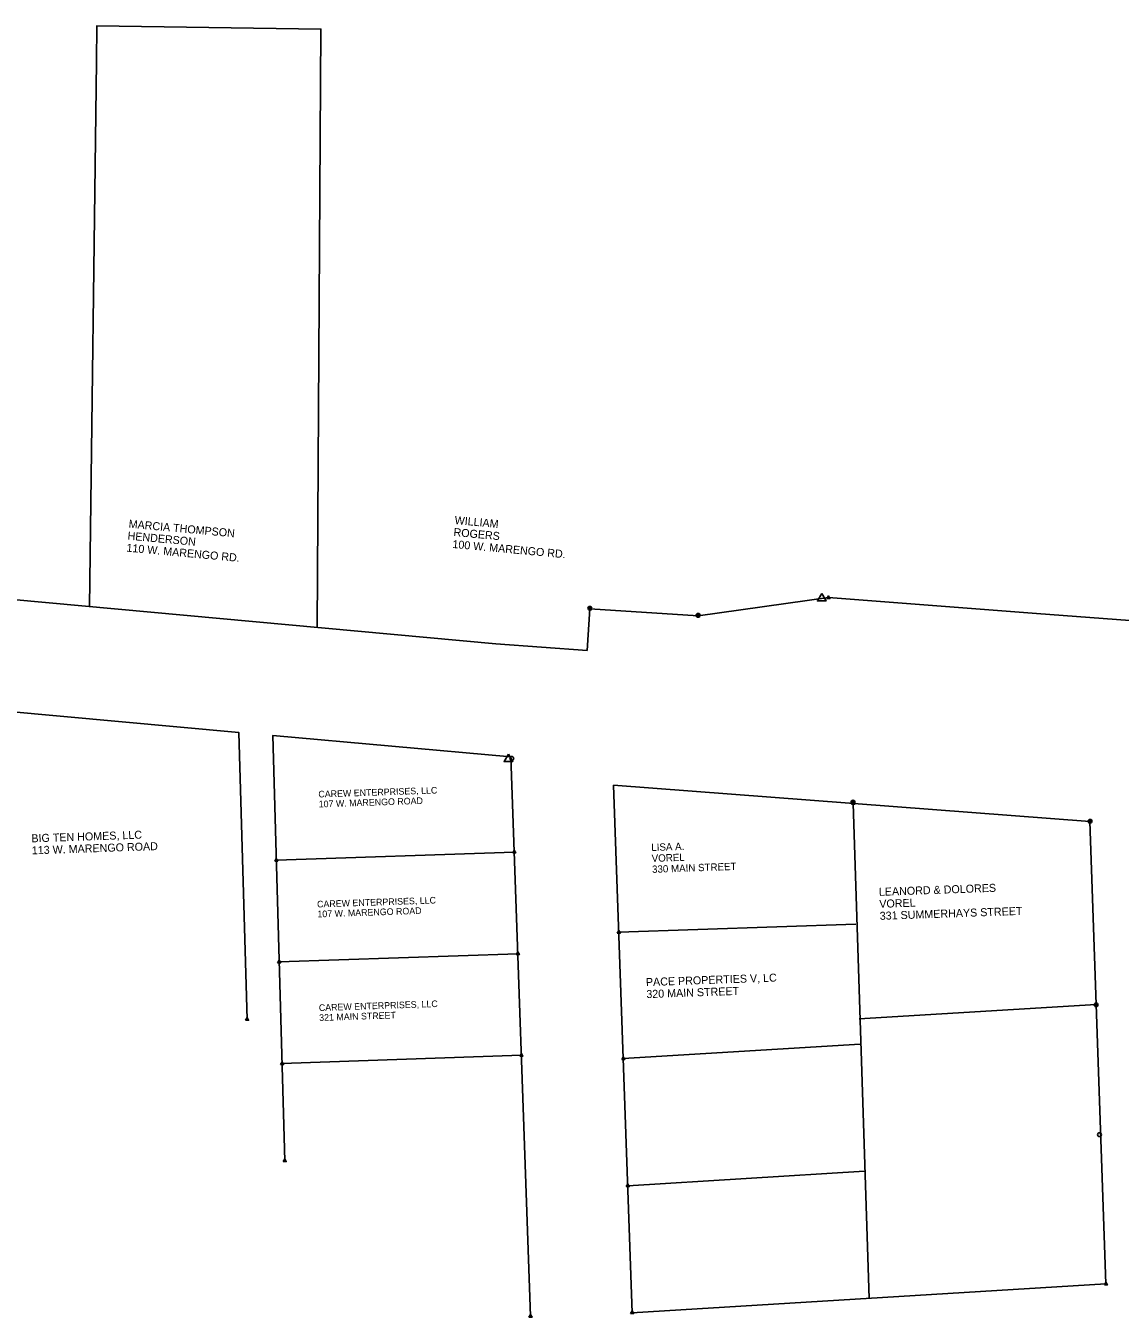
# Model space of a CAD drawing. Extents: x 20500076 to 20505422, y 7951999 to 7957351.
# Drawn here: x 20500631 to 20501277, y 7953599 to 7954361 of the extents above; entities that cross this region are included whole.
import ezdxf

# ---------------------------------------------------------------- set-up
doc = ezdxf.new("R2010")
doc.units = 0
for name, color, linetype in [('DisROW Existing', 7, 'Continuous'), ('DisROW Property Lines', 7, 'Continuous'), ('rowdsnSymbolsProposed', 7, 'Continuous'), ('SurControl', 7, 'Continuous'), ('SurSectionCorner', 7, 'Continuous'), ('Text', 7, 'Continuous')]:
    doc.layers.add(name, color=color, linetype=linetype)

msp = doc.modelspace()

# ---------------------------------------------------------------- linework, layer by layer
at = {"layer": 'DisROW Existing'}
for p, q in [((20501104.8, 7954023.86), (20501227.63, 7954014.51)), ((20500962.39, 7953992.58), (20500964.02, 7954017.27)), ((20500917.43, 7953929.81), (20500928.99, 7953599.7)), ((20500978.05, 7953913.16), (20500988.96, 7953601.8)), ((20500978.05, 7953913.16), (20501258.97, 7953891.76)), ((20501258.97, 7953891.76), (20501268.53, 7953618.77))]:
    msp.add_line(p, q, dxfattribs=at)
for points in [[(20500156.22, 7954065.61), (20500908.59, 7953996.67), (20500962.39, 7953992.58)], [(20501104.8, 7954023.86), (20501027.88, 7954013.05), (20500964.02, 7954017.27)], [(20500622.72, 7953770.22), (20500617.08, 7953957.11), (20500756.81, 7953944.3), (20500761.71, 7953774.91)], [(20500783.96, 7953691.52), (20500776.87, 7953942.47), (20500917.43, 7953929.81)]]:
    msp.add_lwpolyline(points, dxfattribs=at)
msp.add_arc((20498089.14, 7912778.84), 41354.94, 84.948602, 85.647544, dxfattribs=at)
at = {"layer": 'DisROW Property Lines'}
for p, q in [((20501128.74, 7953610.28), (20501119.32, 7953902.4)), ((20500779, 7953868.86), (20500919.4, 7953873.68)), ((20500981.09, 7953826.44), (20501121.01, 7953831.16)), ((20500780.74, 7953808.9), (20500921.5, 7953813.71)), ((20501122.97, 7953775.24), (20501262.76, 7953783.72)), ((20500782.3, 7953748.81), (20500923.6, 7953753.81)), ((20500983.71, 7953751.76), (20501123.49, 7953760.24)), ((20500986.33, 7953676.75), (20501126.12, 7953685.26)), ((20500988.86, 7953601.79), (20501268.53, 7953618.77))]:
    msp.add_line(p, q, dxfattribs=at)
msp.add_lwpolyline([(20500803.09, 7954006.27), (20500805.29, 7954359.4), (20500673.16, 7954361.37), (20500672.92, 7954340.1), (20500668.81, 7954018.64)], dxfattribs=at)
at = {"layer": 'rowdsnSymbolsProposed'}
for points in [[(20501104.8, 7954023.86), (20501104.8, 7954023.86)], [(20500668.81, 7954018.64), (20500668.82, 7954018.65)], [(20500964.02, 7954017.27), (20500964.02, 7954017.27)], [(20501027.88, 7954013.05), (20501027.89, 7954013.05)], [(20500803.09, 7954006.27), (20500803.09, 7954006.28)], [(20500962.39, 7953992.58), (20500962.39, 7953992.58)]]:
    msp.add_lwpolyline(points, dxfattribs=at)
at = {"layer": 'SurControl'}
for points in [[(20501100.86, 7954026.35), (20501103.41, 7954021.94), (20501098.31, 7954021.94)], [(20500915.92, 7953931.49), (20500918.47, 7953927.08), (20500913.37, 7953927.08)]]:
    msp.add_lwpolyline(points, close=True, dxfattribs=at)
for centre in [(20500964.01, 7954017.6), (20500964.03, 7954017.6), (20501027.85, 7954013.45), (20500917.94, 7953928.97), (20501119.29, 7953903.15), (20501259.19, 7953891.88), (20501262.73, 7953783.5), (20501264.76, 7953706.89)]:
    msp.add_circle(centre, 1.12, dxfattribs=at)
at = {"layer": 'SurSectionCorner'}
for points in [[(20501103.88, 7954023.33), (20501105.71, 7954023.33), (20501104.8, 7954024.92)], [(20500963.11, 7954016.74), (20500964.94, 7954016.74), (20500964.02, 7954018.32)], [(20501026.97, 7954012.52), (20501028.8, 7954012.52), (20501027.88, 7954014.1)], [(20501118.41, 7953901.87), (20501120.23, 7953901.87), (20501119.32, 7953903.46)], [(20501258.06, 7953891.23), (20501259.89, 7953891.23), (20501258.97, 7953892.82)], [(20500778.04, 7953868.33), (20500779.86, 7953868.33), (20500778.95, 7953869.91)], [(20500918.49, 7953873.16), (20500920.31, 7953873.16), (20500919.4, 7953874.74)], [(20500980.18, 7953825.91), (20500982, 7953825.91), (20500981.09, 7953827.49)], [(20500920.59, 7953813.18), (20500922.41, 7953813.18), (20500921.5, 7953814.77)], [(20500779.73, 7953808.37), (20500781.56, 7953808.37), (20500780.64, 7953809.96)], [(20501261.84, 7953783.19), (20501263.67, 7953783.19), (20501262.76, 7953784.78)], [(20500760.8, 7953774.38), (20500762.62, 7953774.38), (20500761.71, 7953775.97)], [(20500922.68, 7953753.28), (20500924.51, 7953753.28), (20500923.6, 7953754.86)], [(20500781.42, 7953748.29), (20500783.25, 7953748.29), (20500782.34, 7953749.87)], [(20500982.79, 7953751.23), (20500984.62, 7953751.23), (20500983.71, 7953752.81)], [(20500783.04, 7953690.99), (20500784.87, 7953690.99), (20500783.96, 7953692.58)], [(20500985.42, 7953676.22), (20500987.25, 7953676.22), (20500986.33, 7953677.81)], [(20501267.62, 7953618.24), (20501269.45, 7953618.24), (20501268.53, 7953619.83)], [(20500928.08, 7953599.17), (20500929.91, 7953599.17), (20500928.99, 7953600.75)], [(20500988.04, 7953601.27), (20500989.87, 7953601.27), (20500988.96, 7953602.86)]]:
    msp.add_lwpolyline(points, close=True, dxfattribs=at)

# ---------------------------------------------------------------- texts
at = {"layer": 'Text'}
for s, height, rotation, p in [('MARCIA THOMPSON', 4.7244, 354.76449, (20500691.7, 7954065.19)), ('WILLIAM', 4.724, 354.76449, (20500884.05, 7954067.34)), ('HENDERSON', 4.724, 354.76449, (20500691.06, 7954058.13)), ('ROGERS', 4.724, 354.76449, (20500883.4, 7954060.28)), ('110 W. MARENGO RD.', 4.7244, 354.76449, (20500690.41, 7954051.07)), ('100 W. MARENGO RD.', 4.7244, 354.76449, (20500882.76, 7954053.22)), ('CAREW ENTERPRISES, LLC', 3.904, 1.96447, (20500803.87, 7953905.88)), ('107 W. MARENGO ROAD', 3.904, 1.96447, (20500804.07, 7953900.02)), ('BIG TEN HOMES, LLC', 4.7244, 1.96447, (20500634.53, 7953879.41)), ('113 W. MARENGO ROAD', 4.7244, 1.96447, (20500634.77, 7953872.32)), ('LISA A. ', 4.3, 2.02478, (20501000.33, 7953874.3)), ('VOREL', 4.3, 2.02478, (20501000.56, 7953867.85)), ('330 MAIN STREET', 4.3004, 2.02478, (20501000.78, 7953861.4)), ('LEANORD & DOLORES', 4.7244, 2.02478, (20501134.64, 7953847.83)), ('CAREW ENTERPRISES, LLC', 3.904, 1.96447, (20500803.09, 7953840.97)), ('VOREL', 4.724, 2.02478, (20501134.89, 7953840.74)), ('107 W. MARENGO ROAD', 3.904, 1.96447, (20500803.29, 7953835.12)), ('331 SUMMERHAYS STREET', 4.7244, 2.02478, (20501135.14, 7953833.66)), ('PACE PROPERTIES V, LC', 4.7244, 2.02478, (20500997.17, 7953794.56)), ('320 MAIN STREET', 4.7244, 2.02478, (20500997.42, 7953787.47)), ('CAREW ENTERPRISES, LLC', 3.904, 1.96447, (20500804.14, 7953779.84)), ('321 MAIN STREET', 3.904, 1.96447, (20500804.34, 7953773.99))]:
    msp.add_text(s, height=height, rotation=rotation, dxfattribs=at).set_placement(p)

doc.saveas('drawing.dxf')
